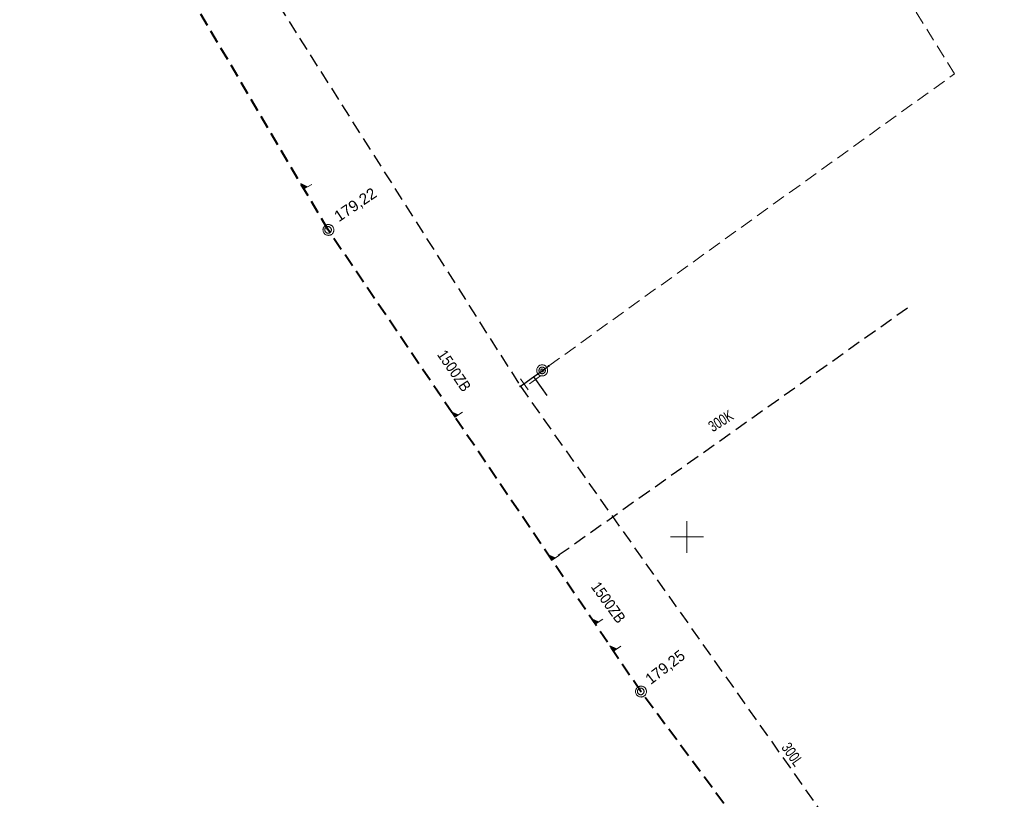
# Model space of a CAD drawing. Extents: x -740851 to -738888, y -1041382 to -1040235.
# Drawn here: x -739360.7 to -739270.7, y -1041173.9 to -1041102.9 of the extents above; entities that cross this region are included whole.
import ezdxf

# ---------------------------------------------------------------- set-up
doc = ezdxf.new("R2010")
doc.units = 0
doc.header["$LTSCALE"] = 0.4
doc.linetypes.add('MEDIUM_DASHED', pattern=[4.5, 3, -1.5])
for name, color, linetype, lineweight in [('1', 7, 'Continuous', 13), ('18', 7, 'Continuous', 13), ('38', 7, 'Continuous', 13), ('8', 7, 'Continuous', 13)]:
    doc.layers.add(name, color=color, linetype=linetype, lineweight=lineweight)

msp = doc.modelspace()

# ---------------------------------------------------------------- linework, layer by layer
at = {"layer": '1'}
for p, q in [((-739300, -1041148.571), (-739300, -1041151.429)), ((-739301.48, -1041150), (-739298.48, -1041150))]:
    msp.add_line(p, q, dxfattribs=at)
at = {"layer": '18', "linetype": 'MEDIUM_DASHED', "lineweight": 40}
for p, q in [((-739332.66, -1041122.02), (-739360.74, -1041074.41)), ((-739312.272, -1041152.11), (-739332.66, -1041122.02)), ((-739304.19, -1041164.07), (-739312.272, -1041152.11))]:
    msp.add_line(p, q, dxfattribs=at)
at = {"layer": '18', "linetype": 'MEDIUM_DASHED', "lineweight": 25}
msp.add_line((-739279.88, -1041129.14), (-739312.272, -1041152.11), dxfattribs=at)
at = {"layer": '18'}
for points in [[(-739334.152, -1041117.878), (-739334.856, -1041118.293), (-739335.152, -1041117.791), (-739334.538, -1041118.106)], [(-739334.631, -1041118.11), (-739334.836, -1041118.231), (-739335.025, -1041117.91), (-739334.629, -1041118.114)], [(-739334.726, -1041118.117), (-739334.829, -1041118.178), (-739334.926, -1041118.013), (-739334.725, -1041118.12)], [(-739320.43, -1041138.615), (-739321.104, -1041139.071), (-739321.43, -1041138.59), (-739320.8, -1041138.865)], [(-739320.892, -1041138.876), (-739321.088, -1041139.009), (-739321.296, -1041138.701), (-739320.89, -1041138.879)], [(-739320.987, -1041138.888), (-739321.085, -1041138.955), (-739321.191, -1041138.797), (-739320.984, -1041138.891)], [(-739311.597, -1041151.651), (-739312.272, -1041152.107), (-739312.597, -1041151.625), (-739311.967, -1041151.901)], [(-739312.059, -1041151.912), (-739312.255, -1041152.044), (-739312.463, -1041151.737), (-739312.057, -1041151.915)], [(-739312.154, -1041151.924), (-739312.252, -1041151.99), (-739312.359, -1041151.833), (-739312.152, -1041151.927)], [(-739307.65, -1041157.492), (-739308.324, -1041157.948), (-739308.65, -1041157.467), (-739308.02, -1041157.743)], [(-739308.112, -1041157.753), (-739308.308, -1041157.886), (-739308.516, -1041157.578), (-739308.11, -1041157.756)], [(-739308.207, -1041157.765), (-739308.305, -1041157.832), (-739308.411, -1041157.674), (-739308.204, -1041157.769)], [(-739305.993, -1041159.945), (-739306.667, -1041160.401), (-739306.993, -1041159.919), (-739306.363, -1041160.195)], [(-739306.454, -1041160.205), (-739306.651, -1041160.338), (-739306.859, -1041160.031), (-739306.452, -1041160.209)], [(-739306.549, -1041160.218), (-739306.647, -1041160.284), (-739306.754, -1041160.126), (-739306.547, -1041160.221)]]:
    msp.add_lwpolyline(points, dxfattribs=at)
for points in [[(-739332.13, -1041122.03), (-739332.14, -1041121.98), (-739332.14, -1041121.93), (-739332.16, -1041121.88), (-739332.18, -1041121.83), (-739332.2, -1041121.78), (-739332.23, -1041121.74), (-739332.26, -1041121.7), (-739332.3, -1041121.66), (-739332.34, -1041121.63), (-739332.38, -1041121.6), (-739332.43, -1041121.58), (-739332.48, -1041121.56), (-739332.53, -1041121.54), (-739332.58, -1041121.54), (-739332.63, -1041121.53), (-739332.68, -1041121.54), (-739332.73, -1041121.54), (-739332.78, -1041121.56), (-739332.83, -1041121.58), (-739332.88, -1041121.6), (-739332.92, -1041121.63), (-739332.96, -1041121.66), (-739333, -1041121.7), (-739333.03, -1041121.74), (-739333.06, -1041121.78), (-739333.08, -1041121.83), (-739333.1, -1041121.88), (-739333.12, -1041121.93), (-739333.12, -1041121.98), (-739333.13, -1041122.03), (-739333.12, -1041122.08), (-739333.12, -1041122.13), (-739333.1, -1041122.18), (-739333.08, -1041122.23), (-739333.06, -1041122.28), (-739333.03, -1041122.32), (-739333, -1041122.36), (-739332.96, -1041122.4), (-739332.92, -1041122.43), (-739332.88, -1041122.46), (-739332.83, -1041122.48), (-739332.78, -1041122.5), (-739332.73, -1041122.52), (-739332.68, -1041122.52), (-739332.63, -1041122.53), (-739332.58, -1041122.52), (-739332.53, -1041122.52), (-739332.48, -1041122.5), (-739332.43, -1041122.48), (-739332.38, -1041122.46), (-739332.34, -1041122.43), (-739332.3, -1041122.4), (-739332.26, -1041122.36), (-739332.23, -1041122.32), (-739332.2, -1041122.28), (-739332.18, -1041122.23), (-739332.16, -1041122.18), (-739332.14, -1041122.13), (-739332.14, -1041122.08)], [(-739332.36, -1041122.02), (-739332.36, -1041121.99), (-739332.366, -1041121.96), (-739332.372, -1041121.93), (-739332.384, -1041121.9), (-739332.402, -1041121.87), (-739332.42, -1041121.846), (-739332.438, -1041121.822), (-739332.462, -1041121.798), (-739332.486, -1041121.78), (-739332.51, -1041121.762), (-739332.54, -1041121.744), (-739332.57, -1041121.732), (-739332.6, -1041121.726), (-739332.63, -1041121.72), (-739332.66, -1041121.72), (-739332.69, -1041121.72), (-739332.72, -1041121.726), (-739332.75, -1041121.732), (-739332.78, -1041121.744), (-739332.81, -1041121.762), (-739332.834, -1041121.78), (-739332.858, -1041121.798), (-739332.882, -1041121.822), (-739332.9, -1041121.846), (-739332.918, -1041121.87), (-739332.936, -1041121.9), (-739332.948, -1041121.93), (-739332.954, -1041121.96), (-739332.96, -1041121.99), (-739332.96, -1041122.02), (-739332.96, -1041122.05), (-739332.954, -1041122.08), (-739332.948, -1041122.11), (-739332.936, -1041122.14), (-739332.918, -1041122.17), (-739332.9, -1041122.194), (-739332.882, -1041122.218), (-739332.858, -1041122.242), (-739332.834, -1041122.26), (-739332.81, -1041122.278), (-739332.78, -1041122.296), (-739332.75, -1041122.308), (-739332.72, -1041122.314), (-739332.69, -1041122.32), (-739332.66, -1041122.32), (-739332.63, -1041122.32), (-739332.6, -1041122.314), (-739332.57, -1041122.308), (-739332.54, -1041122.296), (-739332.51, -1041122.278), (-739332.486, -1041122.26), (-739332.462, -1041122.242), (-739332.438, -1041122.218), (-739332.42, -1041122.194), (-739332.402, -1041122.17), (-739332.384, -1041122.14), (-739332.372, -1041122.11), (-739332.366, -1041122.08), (-739332.36, -1041122.05)], [(-739303.66, -1041164.08), (-739303.67, -1041164.03), (-739303.67, -1041163.98), (-739303.69, -1041163.93), (-739303.71, -1041163.88), (-739303.73, -1041163.83), (-739303.76, -1041163.79), (-739303.79, -1041163.75), (-739303.83, -1041163.71), (-739303.87, -1041163.68), (-739303.91, -1041163.65), (-739303.96, -1041163.63), (-739304.01, -1041163.61), (-739304.06, -1041163.59), (-739304.11, -1041163.59), (-739304.16, -1041163.58), (-739304.21, -1041163.59), (-739304.26, -1041163.59), (-739304.31, -1041163.61), (-739304.36, -1041163.63), (-739304.41, -1041163.65), (-739304.45, -1041163.68), (-739304.49, -1041163.71), (-739304.53, -1041163.75), (-739304.56, -1041163.79), (-739304.59, -1041163.83), (-739304.61, -1041163.88), (-739304.63, -1041163.93), (-739304.65, -1041163.98), (-739304.65, -1041164.03), (-739304.66, -1041164.08), (-739304.65, -1041164.13), (-739304.65, -1041164.18), (-739304.63, -1041164.23), (-739304.61, -1041164.28), (-739304.59, -1041164.33), (-739304.56, -1041164.37), (-739304.53, -1041164.41), (-739304.49, -1041164.45), (-739304.45, -1041164.48), (-739304.41, -1041164.51), (-739304.36, -1041164.53), (-739304.31, -1041164.55), (-739304.26, -1041164.57), (-739304.21, -1041164.57), (-739304.16, -1041164.58), (-739304.11, -1041164.57), (-739304.06, -1041164.57), (-739304.01, -1041164.55), (-739303.96, -1041164.53), (-739303.91, -1041164.51), (-739303.87, -1041164.48), (-739303.83, -1041164.45), (-739303.79, -1041164.41), (-739303.76, -1041164.37), (-739303.73, -1041164.33), (-739303.71, -1041164.28), (-739303.69, -1041164.23), (-739303.67, -1041164.18), (-739303.67, -1041164.13)], [(-739303.89, -1041164.07), (-739303.89, -1041164.04), (-739303.896, -1041164.01), (-739303.902, -1041163.98), (-739303.914, -1041163.95), (-739303.932, -1041163.92), (-739303.95, -1041163.896), (-739303.968, -1041163.872), (-739303.992, -1041163.848), (-739304.016, -1041163.83), (-739304.04, -1041163.812), (-739304.07, -1041163.794), (-739304.1, -1041163.782), (-739304.13, -1041163.776), (-739304.16, -1041163.77), (-739304.19, -1041163.77), (-739304.22, -1041163.77), (-739304.25, -1041163.776), (-739304.28, -1041163.782), (-739304.31, -1041163.794), (-739304.34, -1041163.812), (-739304.364, -1041163.83), (-739304.388, -1041163.848), (-739304.412, -1041163.872), (-739304.43, -1041163.896), (-739304.448, -1041163.92), (-739304.466, -1041163.95), (-739304.478, -1041163.98), (-739304.484, -1041164.01), (-739304.49, -1041164.04), (-739304.49, -1041164.07), (-739304.49, -1041164.1), (-739304.484, -1041164.13), (-739304.478, -1041164.16), (-739304.466, -1041164.19), (-739304.448, -1041164.22), (-739304.43, -1041164.244), (-739304.412, -1041164.268), (-739304.388, -1041164.292), (-739304.364, -1041164.31), (-739304.34, -1041164.328), (-739304.31, -1041164.346), (-739304.28, -1041164.358), (-739304.25, -1041164.364), (-739304.22, -1041164.37), (-739304.19, -1041164.37), (-739304.16, -1041164.37), (-739304.13, -1041164.364), (-739304.1, -1041164.358), (-739304.07, -1041164.346), (-739304.04, -1041164.328), (-739304.016, -1041164.31), (-739303.992, -1041164.292), (-739303.968, -1041164.268), (-739303.95, -1041164.244), (-739303.932, -1041164.22), (-739303.914, -1041164.19), (-739303.902, -1041164.16), (-739303.896, -1041164.13), (-739303.89, -1041164.1)]]:
    msp.add_lwpolyline(points, close=True, dxfattribs=at)
at = {"layer": '18', "linetype": 'MEDIUM_DASHED', "lineweight": 40}
msp.add_lwpolyline([(-739270.72, -1041204.75), (-739278.731, -1041196.38), (-739286.492, -1041187.581), (-739293.4, -1041178.6), (-739304.19, -1041164.07)], dxfattribs=at)
at = {"layer": '38', "linetype": 'MEDIUM_DASHED'}
msp.add_lwpolyline([(-739312.567, -1041134.418), (-739275.615, -1041107.811), (-739300.396, -1041067.826)], dxfattribs=at)
at = {"layer": '8', "linetype": 'MEDIUM_DASHED', "lineweight": 25}
for p, q in [((-739340.075, -1041096.966), (-739315.144, -1041136.272)), ((-739313.18, -1041134.86), (-739312.567, -1041134.418)), ((-739315.144, -1041136.272), (-739280.022, -1041185.98))]:
    msp.add_line(p, q, dxfattribs=at)
at = {"layer": '8'}
for p, q in [((-739312.616, -1041134.467), (-739312.516, -1041134.367)), ((-739312.616, -1041134.367), (-739312.516, -1041134.467)), ((-739312.616, -1041134.367), (-739312.616, -1041134.387)), ((-739312.616, -1041134.367), (-739312.596, -1041134.367)), ((-739312.516, -1041134.367), (-739312.536, -1041134.367)), ((-739312.516, -1041134.367), (-739312.516, -1041134.387)), ((-739312.616, -1041134.467), (-739312.616, -1041134.447)), ((-739312.616, -1041134.467), (-739312.596, -1041134.467)), ((-739312.516, -1041134.467), (-739312.536, -1041134.467)), ((-739312.516, -1041134.467), (-739312.516, -1041134.447)), ((-739314.433, -1041136.58), (-739315.149, -1041135.58)), ((-739314.31, -1041136.049), (-739313.31, -1041135.329)), ((-739315.193, -1041136.321), (-739315.093, -1041136.221)), ((-739315.193, -1041136.221), (-739315.093, -1041136.321)), ((-739315.193, -1041136.221), (-739315.193, -1041136.241)), ((-739315.193, -1041136.221), (-739315.173, -1041136.221)), ((-739315.193, -1041136.321), (-739315.193, -1041136.301)), ((-739315.193, -1041136.321), (-739315.173, -1041136.321)), ((-739315.093, -1041136.221), (-739315.113, -1041136.221)), ((-739315.093, -1041136.321), (-739315.113, -1041136.321)), ((-739315.093, -1041136.221), (-739315.093, -1041136.241)), ((-739315.093, -1041136.321), (-739315.093, -1041136.301))]:
    msp.add_line(p, q, dxfattribs=at)
at = {"layer": '8', "lineweight": 25}
for p, q in [((-739315.144, -1041136.272), (-739314.82, -1041136.04)), ((-739313.948, -1041135.413), (-739313.77, -1041135.66)), ((-739313.77, -1041135.66), (-739312.735, -1041137.1))]:
    msp.add_line(p, q, dxfattribs=at)
at = {"layer": '8'}
for points in [[(-739312.665, -1041134.83), (-739312.665, -1041134.784), (-739312.665, -1041134.724), (-739312.68, -1041134.678), (-739312.695, -1041134.618), (-739312.725, -1041134.572), (-739312.756, -1041134.527), (-739312.786, -1041134.496), (-739312.832, -1041134.451), (-739312.862, -1041134.421), (-739312.907, -1041134.39), (-739312.953, -1041134.36), (-739313.013, -1041134.345), (-739313.059, -1041134.33), (-739313.119, -1041134.33), (-739313.165, -1041134.33), (-739313.225, -1041134.33), (-739313.271, -1041134.33), (-739313.316, -1041134.345), (-739313.377, -1041134.36), (-739313.422, -1041134.39), (-739313.468, -1041134.421), (-739313.498, -1041134.451), (-739313.544, -1041134.496), (-739313.574, -1041134.527), (-739313.604, -1041134.572), (-739313.635, -1041134.618), (-739313.65, -1041134.678), (-739313.665, -1041134.724), (-739313.665, -1041134.784), (-739313.665, -1041134.83), (-739313.665, -1041134.89), (-739313.665, -1041134.936), (-739313.65, -1041134.981), (-739313.635, -1041135.042), (-739313.604, -1041135.087), (-739313.574, -1041135.133), (-739313.544, -1041135.163), (-739313.498, -1041135.208), (-739313.468, -1041135.239), (-739313.422, -1041135.269), (-739313.377, -1041135.299), (-739313.316, -1041135.315), (-739313.271, -1041135.33), (-739313.225, -1041135.33), (-739313.165, -1041135.33), (-739313.119, -1041135.33), (-739313.059, -1041135.33), (-739313.013, -1041135.315), (-739312.953, -1041135.299), (-739312.907, -1041135.269), (-739312.862, -1041135.239), (-739312.832, -1041135.208), (-739312.786, -1041135.163), (-739312.756, -1041135.133), (-739312.725, -1041135.087), (-739312.695, -1041135.042), (-739312.68, -1041134.981), (-739312.665, -1041134.936), (-739312.665, -1041134.89)], [(-739312.516, -1041134.417), (-739312.516, -1041134.412), (-739312.517, -1041134.407), (-739312.518, -1041134.402), (-739312.52, -1041134.397), (-739312.523, -1041134.392), (-739312.526, -1041134.388), (-739312.529, -1041134.384), (-739312.533, -1041134.38), (-739312.537, -1041134.377), (-739312.541, -1041134.374), (-739312.546, -1041134.371), (-739312.551, -1041134.369), (-739312.556, -1041134.368), (-739312.561, -1041134.367), (-739312.566, -1041134.367), (-739312.571, -1041134.367), (-739312.576, -1041134.368), (-739312.581, -1041134.369), (-739312.586, -1041134.371), (-739312.591, -1041134.374), (-739312.595, -1041134.377), (-739312.599, -1041134.38), (-739312.603, -1041134.384), (-739312.606, -1041134.388), (-739312.609, -1041134.392), (-739312.612, -1041134.397), (-739312.614, -1041134.402), (-739312.615, -1041134.407), (-739312.616, -1041134.412), (-739312.616, -1041134.417), (-739312.616, -1041134.422), (-739312.615, -1041134.427), (-739312.614, -1041134.432), (-739312.612, -1041134.437), (-739312.609, -1041134.442), (-739312.606, -1041134.446), (-739312.603, -1041134.45), (-739312.599, -1041134.454), (-739312.595, -1041134.457), (-739312.591, -1041134.46), (-739312.586, -1041134.463), (-739312.581, -1041134.465), (-739312.576, -1041134.466), (-739312.571, -1041134.467), (-739312.566, -1041134.467), (-739312.561, -1041134.467), (-739312.556, -1041134.466), (-739312.551, -1041134.465), (-739312.546, -1041134.463), (-739312.541, -1041134.46), (-739312.537, -1041134.457), (-739312.533, -1041134.454), (-739312.529, -1041134.45), (-739312.526, -1041134.446), (-739312.523, -1041134.442), (-739312.52, -1041134.437), (-739312.518, -1041134.432), (-739312.517, -1041134.427), (-739312.516, -1041134.422)], [(-739312.862, -1041134.83), (-739312.862, -1041134.799), (-739312.877, -1041134.769), (-739312.877, -1041134.739), (-739312.892, -1041134.708), (-739312.907, -1041134.678), (-739312.922, -1041134.648), (-739312.938, -1041134.633), (-739312.968, -1041134.602), (-739312.983, -1041134.587), (-739313.013, -1041134.572), (-739313.044, -1041134.557), (-739313.074, -1041134.542), (-739313.104, -1041134.542), (-739313.135, -1041134.527), (-739313.165, -1041134.527), (-739313.195, -1041134.527), (-739313.225, -1041134.542), (-739313.256, -1041134.542), (-739313.286, -1041134.557), (-739313.316, -1041134.572), (-739313.347, -1041134.587), (-739313.362, -1041134.602), (-739313.392, -1041134.633), (-739313.407, -1041134.648), (-739313.422, -1041134.678), (-739313.438, -1041134.708), (-739313.453, -1041134.739), (-739313.453, -1041134.769), (-739313.468, -1041134.799), (-739313.468, -1041134.83), (-739313.468, -1041134.86), (-739313.453, -1041134.89), (-739313.453, -1041134.921), (-739313.438, -1041134.951), (-739313.422, -1041134.981), (-739313.407, -1041135.012), (-739313.392, -1041135.027), (-739313.362, -1041135.057), (-739313.347, -1041135.072), (-739313.316, -1041135.087), (-739313.286, -1041135.102), (-739313.256, -1041135.118), (-739313.225, -1041135.118), (-739313.195, -1041135.133), (-739313.165, -1041135.133), (-739313.135, -1041135.133), (-739313.104, -1041135.118), (-739313.074, -1041135.118), (-739313.044, -1041135.102), (-739313.013, -1041135.087), (-739312.983, -1041135.072), (-739312.968, -1041135.057), (-739312.938, -1041135.027), (-739312.922, -1041135.012), (-739312.907, -1041134.981), (-739312.892, -1041134.951), (-739312.877, -1041134.921), (-739312.877, -1041134.89), (-739312.862, -1041134.86)], [(-739313.028, -1041134.83), (-739313.028, -1041134.815), (-739313.044, -1041134.799), (-739313.044, -1041134.784), (-739313.044, -1041134.769), (-739313.059, -1041134.769), (-739313.059, -1041134.754), (-739313.074, -1041134.739), (-739313.089, -1041134.724), (-739313.104, -1041134.724), (-739313.104, -1041134.708), (-739313.119, -1041134.708), (-739313.135, -1041134.708), (-739313.15, -1041134.693), (-739313.165, -1041134.693), (-739313.18, -1041134.693), (-739313.195, -1041134.708), (-739313.21, -1041134.708), (-739313.225, -1041134.708), (-739313.225, -1041134.724), (-739313.241, -1041134.724), (-739313.256, -1041134.739), (-739313.271, -1041134.754), (-739313.286, -1041134.769), (-739313.286, -1041134.784), (-739313.286, -1041134.799), (-739313.301, -1041134.815), (-739313.301, -1041134.83), (-739313.301, -1041134.845), (-739313.286, -1041134.86), (-739313.286, -1041134.875), (-739313.286, -1041134.89), (-739313.271, -1041134.905), (-739313.256, -1041134.921), (-739313.241, -1041134.936), (-739313.225, -1041134.951), (-739313.21, -1041134.951), (-739313.195, -1041134.951), (-739313.18, -1041134.966), (-739313.165, -1041134.966), (-739313.15, -1041134.966), (-739313.135, -1041134.951), (-739313.119, -1041134.951), (-739313.104, -1041134.951), (-739313.089, -1041134.936), (-739313.074, -1041134.921), (-739313.059, -1041134.905), (-739313.059, -1041134.89), (-739313.044, -1041134.89), (-739313.044, -1041134.875), (-739313.044, -1041134.86), (-739313.028, -1041134.845)], [(-739315.093, -1041136.271), (-739315.093, -1041136.266), (-739315.094, -1041136.261), (-739315.095, -1041136.256), (-739315.097, -1041136.251), (-739315.1, -1041136.246), (-739315.103, -1041136.242), (-739315.106, -1041136.238), (-739315.11, -1041136.234), (-739315.114, -1041136.231), (-739315.118, -1041136.228), (-739315.123, -1041136.225), (-739315.128, -1041136.223), (-739315.133, -1041136.222), (-739315.138, -1041136.221), (-739315.143, -1041136.221), (-739315.148, -1041136.221), (-739315.153, -1041136.222), (-739315.158, -1041136.223), (-739315.163, -1041136.225), (-739315.168, -1041136.228), (-739315.172, -1041136.231), (-739315.176, -1041136.234), (-739315.18, -1041136.238), (-739315.183, -1041136.242), (-739315.186, -1041136.246), (-739315.189, -1041136.251), (-739315.191, -1041136.256), (-739315.192, -1041136.261), (-739315.193, -1041136.266), (-739315.193, -1041136.271), (-739315.193, -1041136.276), (-739315.192, -1041136.281), (-739315.191, -1041136.286), (-739315.189, -1041136.291), (-739315.186, -1041136.296), (-739315.183, -1041136.3), (-739315.18, -1041136.304), (-739315.176, -1041136.308), (-739315.172, -1041136.311), (-739315.168, -1041136.314), (-739315.163, -1041136.317), (-739315.158, -1041136.319), (-739315.153, -1041136.32), (-739315.148, -1041136.321), (-739315.143, -1041136.321), (-739315.138, -1041136.321), (-739315.133, -1041136.32), (-739315.128, -1041136.319), (-739315.123, -1041136.317), (-739315.118, -1041136.314), (-739315.114, -1041136.311), (-739315.11, -1041136.308), (-739315.106, -1041136.304), (-739315.103, -1041136.3), (-739315.1, -1041136.296), (-739315.097, -1041136.291), (-739315.095, -1041136.286), (-739315.094, -1041136.281), (-739315.093, -1041136.276)]]:
    msp.add_lwpolyline(points, close=True, dxfattribs=at)
at = {"layer": '8', "lineweight": 25}
msp.add_lwpolyline([(-739314.82, -1041136.04), (-739313.948, -1041135.413), (-739313.18, -1041134.86)], dxfattribs=at)

# ---------------------------------------------------------------- texts
at = {"layer": '18'}
for s, rotation, width, p in [('179,22', 33.967, 1.05, (-739331.684, -1041121.335)), ('1500ZB', 304.264, 0.9, (-739322.774, -1041133.389)), ('300K', 32.187, 0.75, (-739297.624, -1041140.471)), ('1500ZB', 305.824, 0.9, (-739308.772, -1041154.541))]:
    msp.add_text(s, height=1, rotation=rotation, dxfattribs=dict(at, width=width)).set_placement(p)
msp.add_text('179,25', height=1, rotation=37.643, dxfattribs=at).set_placement((-739303.284, -1041163.497))
at = {"layer": '8', "width": 0.75}
msp.add_text('300L', height=1, rotation=305.244, dxfattribs=at).set_placement((-739291.428, -1041169.183))

doc.saveas('drawing.dxf')
